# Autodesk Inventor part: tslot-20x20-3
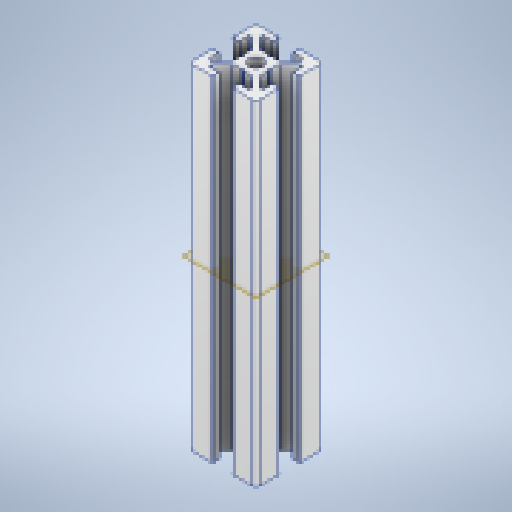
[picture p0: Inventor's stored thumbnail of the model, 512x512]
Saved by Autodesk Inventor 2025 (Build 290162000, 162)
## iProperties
Created: 2025-03
Part Number: tslot-20x20-3
Material: Alluminio 6061
Document SubType Name: Modeling
Designer: Ryzen5700u
Density: 2.7 g/cm^3
Appearance: Alluminio - Piatto
Author: Ryzen5700u
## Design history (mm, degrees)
feature "Base1"
sketch "Schizzo1"
  geometry: L1 (3.761, -16)-(4.7, -16) reference; L2 (3.761, -16)-(0.7, -12.939) reference; L3 (0.7, -12.939)-(0.7, -10.52) reference; L4 (0.4, -10)-(0.7, -10.52) reference; L5 (0.4, -10)-(0.7, -9.48) reference; L6 (0.7, -7.061)-(0.7, -9.48) reference; L7 (3.761, -4)-(0.7, -7.061) reference; L8 (3.761, -4)-(4.7, -4) reference; L9 (4.7, -4)-(4.7, -7) reference; L10 (4.7, -7)-(6.4, -7) reference; L11 (6.7, -6.7)-(6.7, -1) reference; L12 (5.7, 0)-(0, 0) reference; L13 (-0.3, -2)-(-0.3, -0.3) reference; L14 (2.7, -2)-(-0.3, -2) reference; L15 (2.7, -2.939)-(2.7, -2) reference; L16 (2.7, -2.939)-(-0.361, -6) reference; L17 (-0.361, -6)-(-2.78, -6) reference; L18 (-3.3, -6.3)-(-2.78, -6) reference; L19 (-3.3, -6.3)-(-3.82, -6) reference; L20 (-6.239, -6)-(-3.82, -6) reference; L21 (-9.3, -2.939)-(-6.239, -6) reference; L22 (-9.3, -2.939)-(-9.3, -2) reference; L23 (-9.3, -2)-(-6.3, -2) reference; L24 (-6.3, -2)-(-6.3, -0.3) reference; L25 (-12.3, 0)-(-6.6, 0) reference; L26 (-13.3, -6.7)-(-13.3, -1) reference; L27 (-11.3, -7)-(-13, -7) reference; L28 (-11.3, -4)-(-11.3, -7) reference; L29 (-10.361, -4)-(-11.3, -4) reference; L30 (-10.361, -4)-(-7.3, -7.061) reference; L31 (-7.3, -7.061)-(-7.3, -9.48) reference; L32 (-7, -10)-(-7.3, -9.48) reference; L33 (-7, -10)-(-7.3, -10.52) reference; L34 (-7.3, -12.939)-(-7.3, -10.52) reference; L35 (-10.361, -16)-(-7.3, -12.939) reference; L36 (-10.361, -16)-(-11.3, -16) reference; L37 (-11.3, -16)-(-11.3, -13) reference; L38 (-11.3, -13)-(-13, -13) reference; L39 (-13.3, -13.3)-(-13.3, -19) reference; L40 (-12.3, -20)-(-6.6, -20) reference; L41 (-6.3, -18)-(-6.3, -19.7) reference; L42 (-9.3, -18)-(-6.3, -18) reference; L43 (-9.3, -17.061)-(-9.3, -18) reference; L44 (-9.3, -17.061)-(-6.239, -14) reference; L45 (-6.239, -14)-(-3.82, -14) reference; L46 (-3.3, -13.7)-(-3.82, -14) reference; L47 (-3.3, -13.7)-(-2.78, -14) reference; L48 (-0.361, -14)-(-2.78, -14) reference; L49 (2.7, -17.061)-(-0.361, -14) reference; L50 (2.7, -17.061)-(2.7, -18) reference; L51 (2.7, -18)-(-0.3, -18) reference; L52 (-0.3, -18)-(-0.3, -19.7) reference; L53 (5.7, -20)-(0, -20) reference; L54 (6.7, -13.3)-(6.7, -19) reference; L55 (4.7, -13)-(6.4, -13) reference; L56 (4.7, -16)-(4.7, -13) reference; C1 r 2.1 at (-3.3, -10) reference; A1 r 0.3 centre (6.4, -6.7) between (6.4, -7) and (6.7, -6.7) reference; A2 r 1 centre (5.7, -1) between (6.7, -1) and (5.7, 0) reference; A3 r 0.3 centre (0, -0.3) between (0, 0) and (-0.3, -0.3) reference; A4 r 0.3 centre (-6.6, -0.3) between (-6.3, -0.3) and (-6.6, 0) reference; A5 r 1 centre (-12.3, -1) between (-12.3, 0) and (-13.3, -1) reference; A6 r 0.3 centre (-13, -6.7) between (-13.3, -6.7) and (-13, -7) reference; A7 r 0.3 centre (-13, -13.3) between (-13, -13) and (-13.3, -13.3) reference; A8 r 1 centre (-12.3, -19) between (-13.3, -19) and (-12.3, -20) reference; A9 r 0.3 centre (-6.6, -19.7) between (-6.6, -20) and (-6.3, -19.7) reference; A10 r 0.3 centre (0, -19.7) between (-0.3, -19.7) and (0, -20) reference; A11 r 1 centre (5.7, -19) between (5.7, -20) and (6.7, -19) reference; A12 r 0.3 centre (6.4, -13.3) between (6.7, -13.3) and (6.4, -13) reference; 1 further point
extrude "Estrusione1" join sketch "Schizzo1" distance "d0" = 90; taper "d1" = 0 deg
node "Piano di lavoro1"
node "Solido1"
node "Linea chiusa proiettata1"
